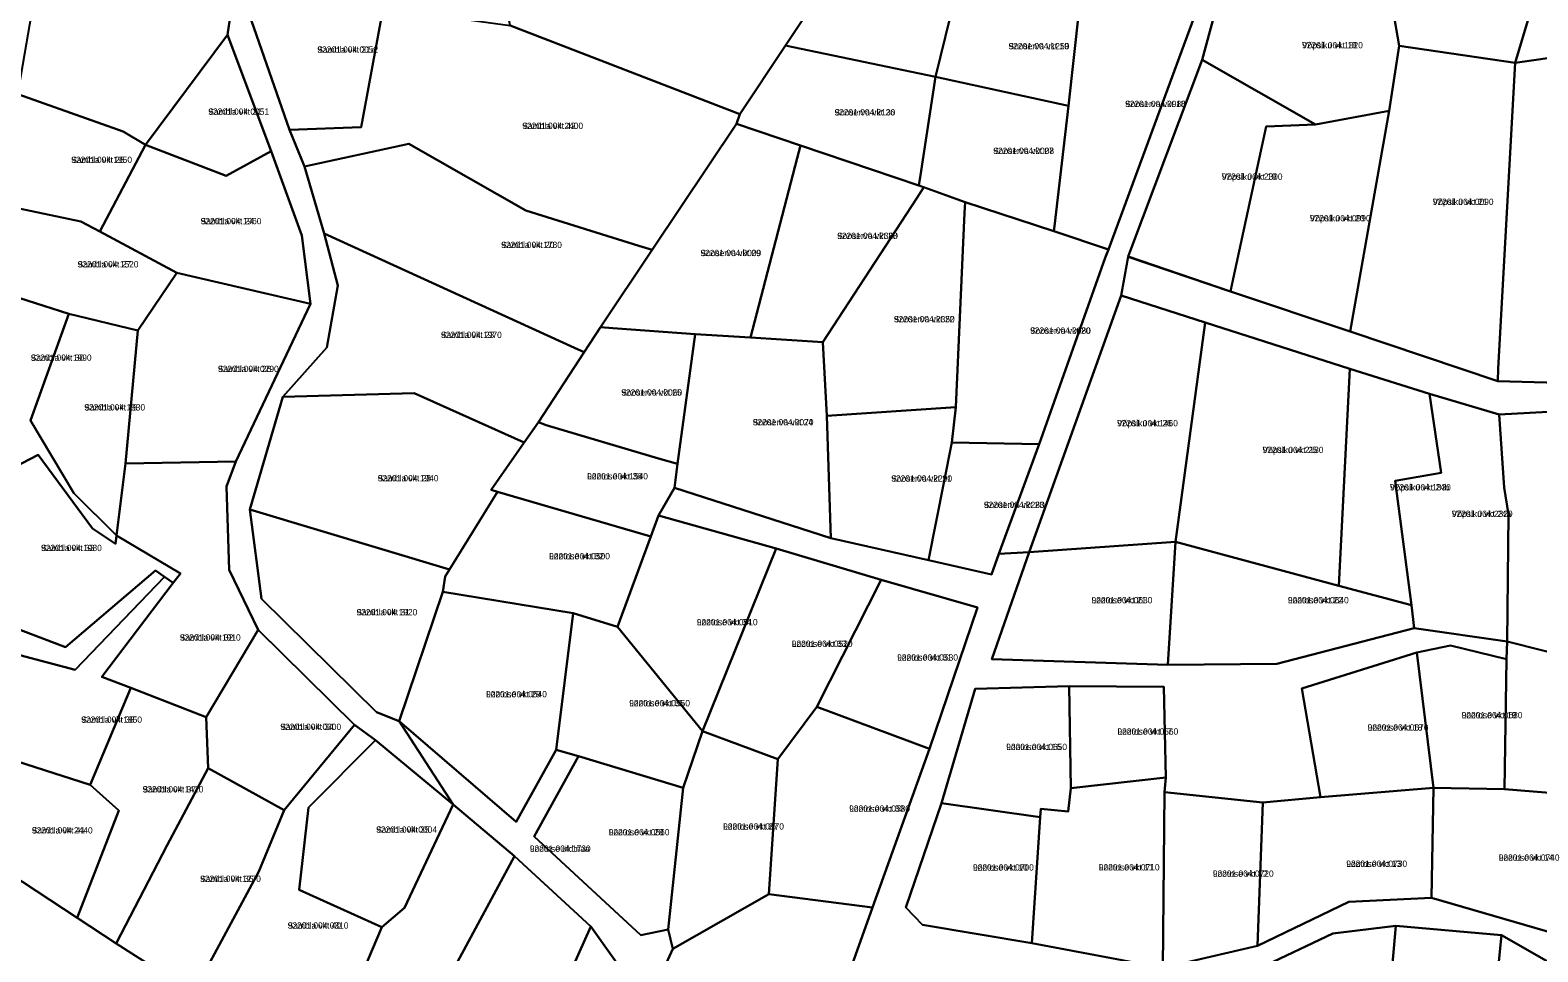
# Model space of a CAD drawing. Extents: x 601493 to 643081, y 6584980 to 6634019.
# Drawn here: x 609641.7 to 610001.3, y 6605239.5 to 6605459.3 of the extents above; entities that cross this region are included whole.
import ezdxf

# ---------------------------------------------------------------- set-up
doc = ezdxf.new("R2010")
doc.units = 0
for name, color, linetype in [('L_AADRESS', 7, 'Continuous'), ('PIIR', 7, 'Continuous'), ('TUNNUS', 7, 'Continuous')]:
    doc.layers.add(name, color=color, linetype=linetype)

msp = doc.modelspace()

# ---------------------------------------------------------------- linework, layer by layer
at = {"layer": 'PIIR'}
for points in [[(609965.23, 6605473.18), (609962.05, 6605524.42), (609965.03, 6605524.54), (609965.63, 6605515.37), (609974.78, 6605513.81), (609994.37, 6605509.95), (609999.94, 6605464.84), (609995.96, 6605451.54), (609968.27, 6605455.6)], [(610058.99, 6605507.43), (610057.58, 6605500.17), (610049.03, 6605459.29), (610021.37, 6605455.21), (609995.96, 6605451.54), (609999.94, 6605464.84), (609994.37, 6605509.95), (610011.74, 6605512.52), (610021.25, 6605513.93), (610037.31, 6605516.37), (610061.39, 6605519.77)], [(609638.8, 6605444.05), (609647, 6605491.64), (609647.66, 6605495.52), (609665.83, 6605488.63), (609686.36, 6605480.71), (609691.83, 6605478.59), (609688.83, 6605458.19), (609669.22, 6605432), (609663.92, 6605435.17)], [(609755.65, 6605463.17), (609750.27, 6605488.22), (609780.85, 6605493.31), (609814.9, 6605486.39), (609836.33, 6605482.03), (609839.04, 6605481.46), (609838.55, 6605480.77), (609821.9, 6605455.66), (609811.03, 6605439.3), (609756.22, 6605460.46)], [(609821.9, 6605455.66), (609838.55, 6605480.77), (609862.37, 6605467.36), (609857.67, 6605448.22), (609823.76, 6605455.28)], [(609694.51, 6605461.52), (609696.76, 6605473.45), (609697.35, 6605476.41), (609712.66, 6605471.26), (609725.96, 6605464.6), (609725.29, 6605461.16), (609720.71, 6605436.15), (609703.63, 6605435.58)], [(609926.24, 6605470.57), (609965.23, 6605473.18), (609968.27, 6605455.6), (609965.91, 6605440.05), (609948.27, 6605436.8), (609921.27, 6605452.23)], [(609857.67, 6605448.22), (609862.37, 6605467.36), (609876.45, 6605467.78), (609892.42, 6605468.27), (609891.96, 6605464.36), (609889.4, 6605441.26)], [(609732.05, 6605432.18), (609707.15, 6605426.83), (609703.63, 6605435.58), (609720.71, 6605436.15), (609725.29, 6605461.16), (609725.96, 6605464.6), (609756.22, 6605460.46), (609811.03, 6605439.3), (609810.19, 6605436.99), (609790.11, 6605406.91), (609786.89, 6605407.92), (609759.99, 6605416.34)], [(609885.87, 6605411.37), (609886.02, 6605412.57), (609889.4, 6605441.26), (609891.96, 6605464.36), (609919.91, 6605463.95), (609898.91, 6605406.97)], [(609699.23, 6605430.48), (609688.52, 6605424.58), (609669.22, 6605432), (609688.83, 6605458.19)], [(609810.19, 6605436.99), (609811.03, 6605439.3), (609821.9, 6605455.66), (609823.76, 6605455.28), (609857.67, 6605448.22), (609854.07, 6605424.73), (609853.69, 6605422.29), (609825.44, 6605431.83)], [(609965.91, 6605440.05), (609968.27, 6605455.6), (609995.96, 6605451.54), (609991.91, 6605378.66), (609991.79, 6605375.64), (609956.58, 6605387.45)], [(609991.91, 6605378.66), (609995.96, 6605451.54), (610021.37, 6605455.21), (610018.01, 6605378.33), (610017.87, 6605374.91), (609991.79, 6605375.64)], [(609904.3, 6605407.24), (609921.27, 6605452.23), (609948.27, 6605436.8), (609936.51, 6605436.35), (609928.41, 6605398.89), (609928.01, 6605397), (609903.6, 6605405.37)], [(609854.07, 6605424.73), (609857.67, 6605448.22), (609889.4, 6605441.26), (609886.02, 6605412.57), (609885.87, 6605411.37), (609864.74, 6605418.32), (609853.69, 6605422.29)], [(609638.8, 6605444.05), (609663.92, 6605435.17), (609669.22, 6605432), (609658.32, 6605411.27), (609653.79, 6605413.69), (609634.54, 6605417.78)], [(609928.41, 6605398.89), (609936.51, 6605436.35), (609948.27, 6605436.8), (609965.91, 6605440.05), (609956.58, 6605387.45), (609928.01, 6605397)], [(609824.66, 6605428.82), (609813.52, 6605386.01), (609800.31, 6605386.79), (609780.71, 6605388.23), (609777.78, 6605388.45), (609790.11, 6605406.91), (609810.19, 6605436.99), (609825.44, 6605431.83)], [(609658.32, 6605411.27), (609669.22, 6605432), (609688.52, 6605424.58), (609699.23, 6605430.48), (609706.52, 6605410.38), (609708.58, 6605394.08), (609676.69, 6605401.45)], [(609707.15, 6605426.83), (609732.05, 6605432.18), (609759.99, 6605416.34), (609786.89, 6605407.92), (609790.11, 6605406.91), (609777.78, 6605388.45), (609773.9, 6605382.53), (609771.58, 6605383.59), (609711.84, 6605410.81)], [(609813.52, 6605386.01), (609824.66, 6605428.82), (609825.44, 6605431.83), (609853.69, 6605422.29), (609854.91, 6605421.85), (609853.23, 6605419.29), (609830.76, 6605384.89)], [(609830.76, 6605384.89), (609853.23, 6605419.29), (609854.91, 6605421.85), (609864.74, 6605418.32), (609864.57, 6605415.75), (609862.5, 6605369.41), (609831.74, 6605367.32)], [(609862.5, 6605369.41), (609864.57, 6605415.75), (609864.74, 6605418.32), (609885.87, 6605411.37), (609898.91, 6605406.97), (609898.14, 6605404.99), (609882.43, 6605360.55), (609861.56, 6605360.95)], [(609630.99, 6605398.03), (609634.54, 6605417.78), (609653.79, 6605413.69), (609658.32, 6605411.27), (609676.69, 6605401.45), (609667.45, 6605387.68), (609650.95, 6605391.65)], [(609701.97, 6605371.87), (609712.53, 6605383.62), (609715.16, 6605398.45), (609711.84, 6605410.81), (609771.58, 6605383.59), (609773.9, 6605382.53), (609762.96, 6605365.82), (609759.59, 6605360.99), (609733.31, 6605372.71)], [(609676.69, 6605401.45), (609708.58, 6605394.08), (609690.78, 6605356.46), (609664.45, 6605355.97), (609667.45, 6605387.68)], [(609630.99, 6605398.03), (609650.95, 6605391.65), (609641.84, 6605366.23), (609652.18, 6605348.91), (609662.31, 6605338.83), (609662.06, 6605336.83), (609656.61, 6605340.47), (609643.67, 6605358.02), (609621.47, 6605346.5)], [(609921.97, 6605389.59), (609914.92, 6605337.28), (609880, 6605334.79), (609901.94, 6605396.07)], [(609641.84, 6605366.23), (609650.95, 6605391.65), (609667.45, 6605387.68), (609664.45, 6605355.97), (609662.31, 6605338.83), (609652.18, 6605348.91)], [(609921.97, 6605389.59), (609956.47, 6605378.55), (609953.89, 6605326.81), (609914.92, 6605337.28)], [(609762.96, 6605365.82), (609773.9, 6605382.53), (609777.78, 6605388.45), (609780.71, 6605388.23), (609800.31, 6605386.79), (609796.15, 6605355.9), (609791.61, 6605357.2), (609764.78, 6605365.13)], [(609813.52, 6605386.01), (609830.76, 6605384.89), (609831.74, 6605367.32), (609832.72, 6605338.16), (609795.44, 6605350.16), (609796.15, 6605355.9), (609800.31, 6605386.79)], [(609956.47, 6605378.55), (609975.52, 6605372.61), (609978.27, 6605353.71), (609967.32, 6605351.84), (609971.2, 6605322.16), (609953.89, 6605326.81)], [(609701.97, 6605371.87), (609733.31, 6605372.71), (609759.59, 6605360.99), (609751.73, 6605349.66), (609753.17, 6605349.25), (609741.76, 6605330.7), (609694.14, 6605344.96)], [(609971.2, 6605322.16), (609967.32, 6605351.84), (609978.27, 6605353.71), (609975.52, 6605372.61), (609992.12, 6605367.68), (609993.27, 6605350.24), (609994.3, 6605343.83), (609994.02, 6605313.53), (609971.86, 6605316.71)], [(609831.74, 6605367.32), (609862.5, 6605369.41), (609861.56, 6605360.95), (609855.98, 6605332.91), (609832.72, 6605338.16)], [(609994.3, 6605343.83), (609993.27, 6605350.24), (609992.12, 6605367.68), (610030.1, 6605369.75), (610019.24, 6605307.15), (609994.02, 6605313.53)], [(609751.73, 6605349.66), (609759.59, 6605360.99), (609762.96, 6605365.82), (609764.78, 6605365.13), (609791.61, 6605357.2), (609796.15, 6605355.9), (609795.44, 6605350.16), (609791.64, 6605343.59), (609789.77, 6605338.52), (609753.17, 6605349.25)], [(609861.56, 6605360.95), (609882.43, 6605360.55), (609872.79, 6605334.39), (609871, 6605329.51), (609855.98, 6605332.91)], [(609620.17, 6605339.42), (609621.47, 6605346.5), (609643.67, 6605358.02), (609656.61, 6605340.47), (609662.06, 6605336.83), (609662.31, 6605338.83), (609677.6, 6605329.77), (609675.85, 6605327.47), (609673.77, 6605328.93), (609671.64, 6605330.42), (609650.17, 6605312.15), (609619.63, 6605323.78)], [(609658.8, 6605305.07), (609675.85, 6605327.47), (609677.6, 6605329.77), (609662.31, 6605338.83), (609664.45, 6605355.97), (609690.78, 6605356.46), (609688.59, 6605350.51), (609689.21, 6605330.6), (609696.09, 6605316.29), (609683.72, 6605295.45), (609665.71, 6605302.48)], [(609740.72, 6605329.01), (609741.76, 6605330.7), (609753.17, 6605349.25), (609789.77, 6605338.52), (609781.83, 6605317), (609771.23, 6605320.31), (609740.18, 6605325.39)], [(609694.14, 6605344.96), (609741.76, 6605330.7), (609740.72, 6605329.01), (609740.18, 6605325.39), (609729.74, 6605294.53), (609724.34, 6605296.66), (609696.9, 6605323.66)], [(609819.66, 6605335.67), (609802.06, 6605292.12), (609781.83, 6605317), (609789.77, 6605338.52), (609791.64, 6605343.59)], [(609844.72, 6605328.23), (609829.34, 6605297.94), (609820.09, 6605285.47), (609802.06, 6605292.12), (609819.66, 6605335.67)], [(609880, 6605334.79), (609914.92, 6605337.28), (609913.11, 6605307.98), (609871.14, 6605309.32)], [(609914.92, 6605337.28), (609953.89, 6605326.81), (609971.2, 6605322.16), (609971.86, 6605316.71), (609939.07, 6605308.2), (609913.11, 6605307.98)], [(609617.8, 6605270.7), (609619.63, 6605323.78), (609650.17, 6605312.15), (609671.64, 6605330.42), (609673.77, 6605328.93), (609652.46, 6605306.76), (609639.25, 6605310.26), (609631.98, 6605287.01), (609629.73, 6605287.84), (609623.3, 6605267.08)], [(609639.25, 6605310.26), (609652.46, 6605306.76), (609673.77, 6605328.93), (609675.85, 6605327.47), (609658.8, 6605305.07), (609665.71, 6605302.48), (609656.04, 6605279.3), (609631.98, 6605287.01)], [(609771.23, 6605320.31), (609767.16, 6605287.65), (609757.67, 6605270.54), (609729.74, 6605294.53), (609740.18, 6605325.39)], [(609867.71, 6605321.64), (609856.25, 6605287.91), (609829.34, 6605297.94), (609844.72, 6605328.23)], [(609781.83, 6605317), (609802.06, 6605292.12), (609797.52, 6605278.63), (609772.52, 6605286.2), (609767.16, 6605287.65), (609771.23, 6605320.31)], [(609719.09, 6605293.61), (609702.3, 6605273.3), (609684.19, 6605283.33), (609683.72, 6605295.45), (609696.09, 6605316.29)], [(609945.02, 6605302.28), (609972.51, 6605310.87), (609976.47, 6605278.63), (609949.52, 6605276.42)], [(609972.51, 6605310.87), (609980.52, 6605312.55), (609993.83, 6605309.34), (609993.36, 6605278.27), (609976.47, 6605278.63)], [(610019.24, 6605307.15), (610034.6, 6605303.37), (610033.28, 6605275.26), (610009.98, 6605276.91), (609993.36, 6605278.27), (609993.83, 6605309.34), (609994.02, 6605313.53)], [(609652.94, 6605247.61), (609662.9, 6605273.18), (609656.04, 6605279.3), (609665.71, 6605302.48), (609683.72, 6605295.45), (609684.19, 6605283.33), (609674.45, 6605264.97), (609662.24, 6605241.51)], [(609867.13, 6605302.25), (609889.53, 6605302.9), (609889.94, 6605278.51), (609889.29, 6605272.95), (609882.82, 6605273.63), (609882.67, 6605271.64), (609859.13, 6605274.92)], [(609889.53, 6605302.9), (609912.13, 6605302.74), (609912.6, 6605281.08), (609889.94, 6605278.51)], [(609856.25, 6605287.91), (609842.64, 6605250.04), (609817.92, 6605253.23), (609820.09, 6605285.47), (609829.34, 6605297.94)], [(609724.08, 6605289.99), (609708.16, 6605273.89), (609705.92, 6605254.31), (609725.62, 6605245.35), (609716.7, 6605224.4), (609709.96, 6605211.48), (609680.7, 6605229.72), (609696.27, 6605258.69), (609702.3, 6605273.3), (609719.09, 6605293.61)], [(609582.15, 6605291.72), (609617.8, 6605270.7), (609623.3, 6605267.08), (609652.94, 6605247.61), (609662.24, 6605241.51), (609680.7, 6605229.72), (609709.96, 6605211.48), (609805.07, 6605150.6), (609683.13, 6604912.06), (609663.14, 6604927.61), (609612.62, 6604968.35), (609547.75, 6605023.33), (609498.6, 6605068.29), (609474.98, 6605090.91), (609483.64, 6605178.98), (609580.67, 6605224.04)], [(609724.08, 6605289.99), (609742.61, 6605274.66), (609731, 6605250), (609725.62, 6605245.35), (609705.92, 6605254.31), (609708.16, 6605273.89)], [(609820.09, 6605285.47), (609817.92, 6605253.23), (609794.99, 6605240.2), (609793.94, 6605244.82), (609797.52, 6605278.63), (609802.06, 6605292.12)], [(609629.73, 6605287.84), (609631.98, 6605287.01), (609656.04, 6605279.3), (609662.9, 6605273.18), (609652.94, 6605247.61), (609623.3, 6605267.08)], [(609797.52, 6605278.63), (609793.94, 6605244.82), (609787.37, 6605243.47), (609761.93, 6605266.97), (609772.52, 6605286.2)], [(609662.24, 6605241.51), (609674.45, 6605264.97), (609684.19, 6605283.33), (609702.3, 6605273.3), (609696.27, 6605258.69), (609680.7, 6605229.72)], [(609882.67, 6605271.64), (609882.82, 6605273.63), (609889.29, 6605272.95), (609889.94, 6605278.51), (609912.6, 6605281.08), (609912.31, 6605277.57), (609911.86, 6605235.71), (609880.64, 6605241.53)], [(609934.48, 6605240.91), (609935.78, 6605275.08), (609949.52, 6605276.42), (609976.47, 6605278.63), (609975.97, 6605252.38), (609956.22, 6605251.46)], [(609976.47, 6605278.63), (609993.36, 6605278.27), (610009.98, 6605276.91), (610005.54, 6605243.82), (609975.97, 6605252.38)], [(609757.23, 6605262.31), (609728.2, 6605208.48), (609709.96, 6605211.48), (609716.7, 6605224.4), (609725.62, 6605245.35), (609731, 6605250), (609742.61, 6605274.66)], [(609850.56, 6605250.11), (609859.13, 6605274.92), (609882.67, 6605271.64), (609880.64, 6605241.53), (609854.54, 6605245.9)], [(609912.31, 6605277.57), (609935.78, 6605275.08), (609934.48, 6605240.91), (609911.86, 6605235.71)], [(609757.23, 6605262.31), (609775.46, 6605245.55), (609756.6, 6605203.39), (609728.2, 6605208.48)], [(609842.64, 6605250.04), (609826.86, 6605205.68), (609812.41, 6605205.34), (609792.67, 6605234.99), (609794.99, 6605240.2), (609817.92, 6605253.23)], [(609939.69, 6605222.07), (609935.07, 6605222.8), (609935, 6605235.62), (609952.43, 6605243.84), (609967.48, 6605245.73), (609962.78, 6605192.76), (609937.82, 6605190.06)], [(609967.48, 6605245.73), (609992.68, 6605243.51), (609987.83, 6605195.38), (609962.78, 6605192.76)], [(609800.92, 6605209.82), (609788.43, 6605188.22), (609756.6, 6605203.39), (609775.46, 6605245.55)], [(609992.68, 6605243.51), (610032.09, 6605220.95), (610031.21, 6605200.03), (609987.83, 6605195.38)]]:
    msp.add_lwpolyline(points, close=True, dxfattribs=at)
for points in [[(609694.51, 6605461.52), (609703.63, 6605435.58), (609707.15, 6605426.83), (609711.84, 6605410.81), (609715.16, 6605398.45), (609712.53, 6605383.62), (609701.97, 6605371.87), (609694.14, 6605344.96), (609696.9, 6605323.66), (609724.34, 6605296.66), (609729.74, 6605294.53), (609742.61, 6605274.66), (609724.08, 6605289.99), (609719.09, 6605293.61), (609696.09, 6605316.29), (609689.21, 6605330.6), (609688.59, 6605350.51), (609690.78, 6605356.46), (609708.58, 6605394.08), (609706.52, 6605410.38), (609699.23, 6605430.48), (609688.83, 6605458.19), (609691.83, 6605478.59)], [(609926.24, 6605470.57), (609921.27, 6605452.23), (609904.3, 6605407.24), (609903.6, 6605405.37), (609901.94, 6605396.07), (609880, 6605334.79), (609872.79, 6605334.39), (609882.43, 6605360.55), (609898.14, 6605404.99), (609898.91, 6605406.97), (609919.91, 6605463.95)], [(610030.1, 6605369.75), (609992.12, 6605367.68), (609975.52, 6605372.61), (609956.47, 6605378.55), (609921.97, 6605389.59), (609901.94, 6605396.07), (609903.6, 6605405.3), (609928.01, 6605397), (609956.58, 6605387.45), (609991.79, 6605375.64), (610017.87, 6605374.91)], [(609826.86, 6605205.68), (609842.64, 6605250.04), (609856.25, 6605287.91), (609867.71, 6605321.64), (609844.72, 6605328.23), (609819.66, 6605335.67), (609791.64, 6605343.59), (609795.44, 6605350.16), (609832.72, 6605338.16), (609855.98, 6605332.91), (609871, 6605329.51), (609872.79, 6605334.39), (609880, 6605334.79), (609871.14, 6605309.32), (609913.11, 6605307.98), (609939.07, 6605308.2), (609971.86, 6605316.71), (609994.02, 6605313.53), (609993.83, 6605309.34), (609980.52, 6605312.55), (609972.51, 6605310.87), (609945.02, 6605302.28), (609949.52, 6605276.42), (609935.78, 6605275.08), (609912.31, 6605277.57), (609912.6, 6605281.08), (609912.13, 6605302.74), (609889.53, 6605302.9), (609867.13, 6605302.25), (609859.13, 6605274.92), (609850.56, 6605250.11), (609854.54, 6605245.9), (609880.64, 6605241.53), (609911.86, 6605235.71), (609934.48, 6605240.91), (609956.22, 6605251.46), (609975.97, 6605252.38), (610005.54, 6605243.82)], [(609800.92, 6605209.82), (609775.46, 6605245.55), (609757.23, 6605262.31), (609742.61, 6605274.66), (609729.74, 6605294.53), (609757.67, 6605270.54), (609767.16, 6605287.65), (609772.52, 6605286.2), (609761.93, 6605266.97), (609787.37, 6605243.47), (609793.94, 6605244.82), (609794.99, 6605240.2), (609792.67, 6605234.99)], [(610032.09, 6605220.95), (609992.68, 6605243.51), (609967.48, 6605245.73), (609952.43, 6605243.84), (609935, 6605235.62)]]:
    msp.add_lwpolyline(points, dxfattribs=at)

# ---------------------------------------------------------------- texts
at = {"layer": 'L_AADRESS'}
for s, p in [('Sambla vkt 21a', (609710.23, 6605453.94)), ('Sooserva vkt 19', (609875.09, 6605454.77)), ('Võpsiku vkt 18', (609945.1, 6605454.99)), ('Sambla vkt 21', (609684.22, 6605439.14)), ('Sooserva vkt 26', (609833.58, 6605438.98)), ('Sooserva vkt 18', (609902.89, 6605440.98)), ('Sambla vkt 42', (609759.12, 6605435.76)), ('Sambla vkt 25', (609651.54, 6605427.66)), ('Sooserva vkt 27', (609871.45, 6605429.79)), ('Võpsiku vkt 19', (609925.94, 6605423.64)), ('Võpsiku vkt 21', (609976.27, 6605417.64)), ('Võpsiku vkt 20', (609946.96, 6605413.71)), ('Sambla vkt 24', (609682.4, 6605413.04)), ('Sooserva vkt 28', (609834.21, 6605409.52)), ('Sambla vkt 20', (609754.06, 6605407.36)), ('Sambla vkt 27', (609653.07, 6605402.73)), ('Sooserva vkt 29', (609801.61, 6605405.43)), ('Sooserva vkt 22', (609847.75, 6605389.65)), ('Sambla vkt 23', (609739.72, 6605385.9)), ('Sooserva vkt 20', (609880.23, 6605386.91)), ('Sambla vkt 30', (609641.89, 6605380.46)), ('Sambla vkt 26', (609686.52, 6605377.78)), ('Sooserva vkt 25', (609782.73, 6605372.17)), ('Sambla vkt 29', (609654.65, 6605368.61)), ('Sooserva vkt 24', (609814.08, 6605365.07)), ('Võpsiku vkt 26', (609900.98, 6605364.84)), ('Võpsiku vkt 25', (609935.7, 6605358.45)), ('Lootose vkt 36', (609774.58, 6605352.17)), ('Sambla vkt 28', (609724.63, 6605351.71)), ('Sooserva vkt 21', (609847.12, 6605351.64)), ('Võpsiku vkt 24b', (609966.08, 6605349.54)), ('Sooserva vkt 23', (609869.2, 6605345.36)), ('Võpsiku vkt 24a', (609980.81, 6605343.23)), ('Sambla vkt 33', (609644.33, 6605335.08)), ('Lootose vkt 32', (609765.52, 6605333.12)), ('Sambla vkt 31', (609719.57, 6605319.75)), ('Lootose vkt 21', (609894.89, 6605322.63)), ('Lootose vkt 22', (609941.73, 6605322.63)), ('Lootose vkt 34', (609800.74, 6605317.38)), ('Sambla vkt 32', (609677.45, 6605313.73)), ('Lootose vkt 33', (609823.39, 6605312.24)), ('Lootose vkt 31', (609848.53, 6605308.96)), ('Lootose vkt 29', (609750.48, 6605300.21)), ('Lootose vkt 35', (609784.61, 6605298.06)), ('Lootose vkt 19', (609983.17, 6605295.2)), ('Sambla vkt 38', (609653.91, 6605294.13)), ('Sambla vkt 34', (609701.41, 6605292.42)), ('Lootose vkt 17', (609901.07, 6605291.3)), ('Lootose vkt 18', (609960.75, 6605292.27)), ('Lootose vkt 16', (609874.54, 6605287.62)), ('Sambla vkt 37', (609668.56, 6605277.51)), ('Lootose vkt 30', (609837.09, 6605272.91)), ('Sambla vkt 41', (609642.14, 6605267.73)), ('Sambla vkt 35', (609724.27, 6605267.9)), ('Lootose vkt 28', (609779.73, 6605267.28)), ('Lootose vkt 27', (609807.02, 6605268.66)), ('Lootose üldmaa', (609760.91, 6605263.36)), ('Lootose vkt 10', (609866.62, 6605258.88)), ('Lootose vkt 11', (609896.62, 6605258.91)), ('Lootose vkt 13', (609955.65, 6605259.77)), ('Lootose vkt 14', (609992.01, 6605261.23)), ('Sambla vkt 36', (609682.27, 6605256.18)), ('Lootose vkt 12', (609923.82, 6605257.4)), ('Sambla vkt 40', (609703.16, 6605245.03))]:
    msp.add_text(s, height=1.5, dxfattribs=at).set_placement(p)
at = {"layer": 'TUNNUS'}
for s, p in [('92201:004:0052', (609710.23, 6605453.94)), ('92201:004:1250', (609875.09, 6605454.77)), ('92201:004:1820', (609945.1, 6605454.99)), ('92201:004:0051', (609684.22, 6605439.14)), ('92201:004:2130', (609833.58, 6605438.98)), ('92201:004:0980', (609902.89, 6605440.98)), ('92201:004:2400', (609759.12, 6605435.76)), ('92201:004:1950', (609651.54, 6605427.66)), ('92201:004:0008', (609871.45, 6605429.79)), ('92201:004:2300', (609925.94, 6605423.64)), ('92201:004:0090', (609976.27, 6605417.64)), ('92201:004:0990', (609946.96, 6605413.71)), ('92201:004:1960', (609682.4, 6605413.04)), ('92201:004:1780', (609754.06, 6605407.36)), ('92201:004:2360', (609834.21, 6605409.52)), ('92201:004:1520', (609653.07, 6605402.73)), ('92201:004:0009', (609801.61, 6605405.43)), ('92201:004:2350', (609847.75, 6605389.65)), ('92201:004:1970', (609739.72, 6605385.9)), ('92201:004:0080', (609880.23, 6605386.91)), ('92201:004:1990', (609641.89, 6605380.46)), ('92201:004:0290', (609686.52, 6605377.78)), ('92201:004:0060', (609782.73, 6605372.17)), ('92201:004:1930', (609654.65, 6605368.61)), ('92201:004:0070', (609814.08, 6605365.07)), ('92201:004:1460', (609900.98, 6605364.84)), ('92201:004:2180', (609935.7, 6605358.45)), ('92201:004:1540', (609774.58, 6605352.17)), ('92201:004:1940', (609724.63, 6605351.71)), ('92201:004:2290', (609847.12, 6605351.64)), ('92201:004:1830', (609966.08, 6605349.54)), ('92201:004:2280', (609869.2, 6605345.36)), ('92201:004:2320', (609980.81, 6605343.23)), ('92201:004:1980', (609644.33, 6605335.08)), ('92201:004:0500', (609765.52, 6605333.12)), ('92201:004:1920', (609719.57, 6605319.75)), ('92201:004:0630', (609894.89, 6605322.63)), ('92201:004:0640', (609941.73, 6605322.63)), ('92201:004:0510', (609800.74, 6605317.38)), ('92201:004:1910', (609677.45, 6605313.73)), ('92201:004:0520', (609823.39, 6605312.24)), ('92201:004:0530', (609848.53, 6605308.96)), ('92201:004:0540', (609750.48, 6605300.21)), ('92201:004:0550', (609784.61, 6605298.06)), ('92201:004:0680', (609983.17, 6605295.2)), ('92201:004:1850', (609653.91, 6605294.13)), ('92201:004:0300', (609701.41, 6605292.42)), ('92201:004:0660', (609901.07, 6605291.3)), ('92201:004:0670', (609960.75, 6605292.27)), ('92201:004:0650', (609874.54, 6605287.62)), ('92201:004:1410', (609668.56, 6605277.51)), ('92201:004:0580', (609837.09, 6605272.91)), ('92201:004:2440', (609642.14, 6605267.73)), ('92201:004:0004', (609724.27, 6605267.9)), ('92201:004:0560', (609779.73, 6605267.28)), ('92201:004:0570', (609807.02, 6605268.66)), ('92201:004:1730', (609760.91, 6605263.36)), ('92201:004:0700', (609866.62, 6605258.88)), ('92201:004:0710', (609896.62, 6605258.91)), ('92201:004:0730', (609955.65, 6605259.77)), ('92201:004:0740', (609992.01, 6605261.23)), ('92201:004:1270', (609682.27, 6605256.18)), ('92201:004:0720', (609923.82, 6605257.4)), ('92201:004:0310', (609703.16, 6605245.03))]:
    msp.add_text(s, height=1.5, dxfattribs=at).set_placement(p)

doc.saveas('drawing.dxf')
